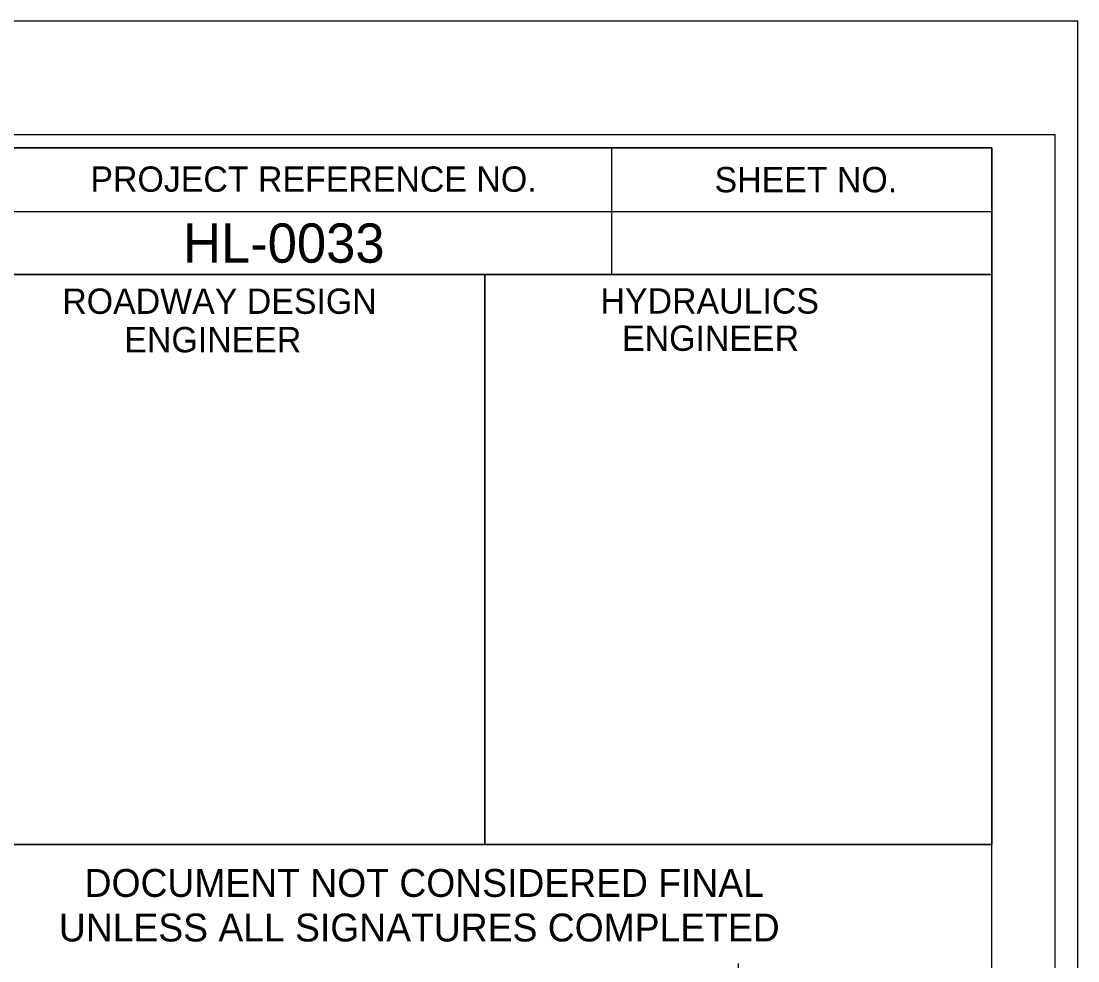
# Model space of a CAD drawing. Extents: x 2044835 to 2046519, y 755505 to 756605.
# Drawn here: x 2046310.1 to 2046518.6, y 756419.9 to 756605.4 of the extents above; entities that cross this region are included whole.
import ezdxf

# ---------------------------------------------------------------- set-up
doc = ezdxf.new("R2010")
doc.units = 0
for name, color, linetype in [('Sheet Cutting Line CELL', 7, 'Continuous'), ('Sheet Data Field CELL', 7, 'Continuous'), ('Sheet Plot Border Inside CELL', 7, 'Continuous'), ('Sheet Plot Border Outside CELL', 7, 'Continuous'), ('Sheet Profile CELL', 7, 'Continuous'), ('Sheet Profile Grid Major CELL', 7, 'Continuous'), ('Sheet Sticker Exception Certification CELL', 7, 'Continuous')]:
    doc.layers.add(name, color=color, linetype=linetype)

msp = doc.modelspace()

# ---------------------------------------------------------------- linework, layer by layer
at = {"layer": 'Sheet Cutting Line CELL'}
msp.add_line((2046518.63, 756605.41), (2044834.63, 756605.41), dxfattribs=at)
at = {"layer": 'Sheet Plot Border Inside CELL'}
msp.add_lwpolyline([(2044847.63, 755527.86), (2046514.13, 755527.86), (2046514.13, 756582.96), (2044847.63, 756582.96)], close=True, dxfattribs=at)
at = {"layer": 'Sheet Plot Border Outside CELL'}
msp.add_lwpolyline([(2044834.63, 755505.41), (2046518.63, 755505.41), (2046518.63, 756605.41), (2044834.63, 756605.41)], close=True, dxfattribs=at)
at = {"layer": 'Sheet Profile CELL'}
for p, q in [((2046426.63, 756580.36), (2046426.63, 756555.36)), ((2046301.58, 756567.86), (2046501.63, 756567.86)), ((2046401.63, 756555.36), (2046401.63, 756442.91))]:
    msp.add_line(p, q, dxfattribs=at)
for points in [[(2046501.63, 756580.41), (2045001.63, 756580.41), (2045001.63, 755530.41), (2046501.63, 755530.41)], [(2046301.58, 756580.41), (2046501.63, 756580.41), (2046501.63, 756555.36), (2046301.58, 756555.36)], [(2046301.58, 756555.36), (2046401.63, 756555.36), (2046401.63, 756442.86), (2046301.58, 756442.86)], [(2046401.63, 756555.36), (2046501.63, 756555.36), (2046501.63, 756442.86), (2046401.63, 756442.86)]]:
    msp.add_lwpolyline(points, close=True, dxfattribs=at)
at = {"layer": 'Sheet Profile Grid Major CELL'}
for points in [[(2046251.63, 756480.37), (2046251.63, 756080.41), (2046301.63, 756080.41), (2046301.63, 756580.41), (2046327.93, 756580.41)], [(2046451.63, 756419.36), (2046451.63, 756080.41), (2046501.63, 756080.41), (2046501.63, 756430.41)]]:
    msp.add_lwpolyline(points, dxfattribs=at)
at = {"layer": 'Sheet Sticker Exception Certification CELL'}
for p, q in [((2046301.58, 756442.86), (2046501.62, 756442.86)), ((2046301.58, 756442.86), (2046501.62, 756442.86)), ((2046501.62, 756442.85), (2046501.62, 756419.35)), ((2046501.62, 756442.85), (2046501.62, 756419.35))]:
    msp.add_line(p, q, dxfattribs=at)

# ---------------------------------------------------------------- texts
at = {"layer": 'Sheet Data Field CELL'}
msp.add_text('HL-0033', height=7.75, dxfattribs=at).set_placement((2046342.09, 756557.72))
at = {"layer": 'Sheet Profile CELL'}
for s, height, p in [('PROJECT REFERENCE NO.', 5.0001, (2046323.8, 756571.72)), ('SHEET NO.', 5, (2046446.95, 756571.62)), ('ROADWAY DESIGN', 5.0001, (2046318.25, 756547.62)), ('HYDRAULICS', 5, (2046424.45, 756547.67)), ('ENGINEER', 5, (2046330.5, 756540.02)), ('ENGINEER', 5, (2046428.7, 756540.32))]:
    msp.add_text(s, height=height, dxfattribs=at).set_placement(p)
at = {"layer": 'Sheet Sticker Exception Certification CELL'}
for s, p in [('DOCUMENT NOT CONSIDERED FINAL', (2046322.66, 756432.52)), ('DOCUMENT NOT CONSIDERED FINAL', (2046322.66, 756432.52)), ('UNLESS ALL SIGNATURES COMPLETED', (2046317.58, 756423.72)), ('UNLESS ALL SIGNATURES COMPLETED', (2046317.58, 756423.72))]:
    msp.add_text(s, height=5.5, dxfattribs=at).set_placement(p)

doc.saveas('drawing.dxf')
